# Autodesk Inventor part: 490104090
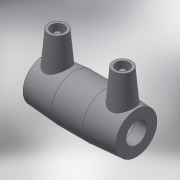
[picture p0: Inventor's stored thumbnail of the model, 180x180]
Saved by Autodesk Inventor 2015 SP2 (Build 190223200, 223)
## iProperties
Created: 2017-06
Part Number: 490104090
Material: Generic
Description: PLASSON COUPLER 90-90
Document SubType Name: Modeling
Designer: KIM
Mass: 55.0731 g
Surface Area: 148.067 cm^2
Volume: 55.0731 cm^3
Density: 1 g/cm^3
Appearance: Default
Author: KIM
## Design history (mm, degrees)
derived "490104.ipt"
feature "Solid1::490104.ipt"
tag "TaggingFeature1"
body "Solid1"
other parameters: "d0" = 148, "d2" = 112, "d3" = 73, "d4" = 49.33333, "d5" = 100.8, "d6" = 85.5, "d8" = 168 deg, "d10" = 29.2, "d11" = 9.73333, "d13" = 148, "d14" = 17.6296, "d15" = 73, "d16" = 73, "d17" = 85.5, "d19" = 3.52592, "d20" = 168 deg, "d22" = 105.28, "d23" = 112, "d24" = 102.1216, "d25" = 135 deg, "d26" = 59.2, "d27" = 135 deg, "d29" = 71, "d30" = 14, "d31" = 51.8, "d34" = 5 deg, "d35" = 15, "d39" = 5 deg, "d41" = 4, "d42" = 14, "d43" = 0, "d45" = 4, "d46" = 14, "d47" = 0, "d48" = 3, "d49" = 0, "d50" = 3, "d51" = 0, "d52" = 21.17, "d53" = 5.2925, "L_" = 148, "L_1" = 73, "D_" = 112, "A_" = 71, "d_2" = 12
